Omron CX-Programmer project NuevoProyecto (CX-Programmer 9.50)

# PLC NewPLC1: CP1L-E EM

## Program P1_Apendice (cyclic task 0)
Local symbols
Etapa_0 10.00 BOOL
Etapa_1 10.01 BOOL
Etapa_2 10.02 BOOL
Etapa_3 10.03 BOOL
Etapa_4 10.04 BOOL
F1 0.01 BOOL
F2 0.02 BOOL
Rd 100.00 BOOL
Ri 100.01 BOOL
m 0.00 BOOL

### Section Sección1_Programa_principal
; Programa principal (Etapas 0 ... 4)

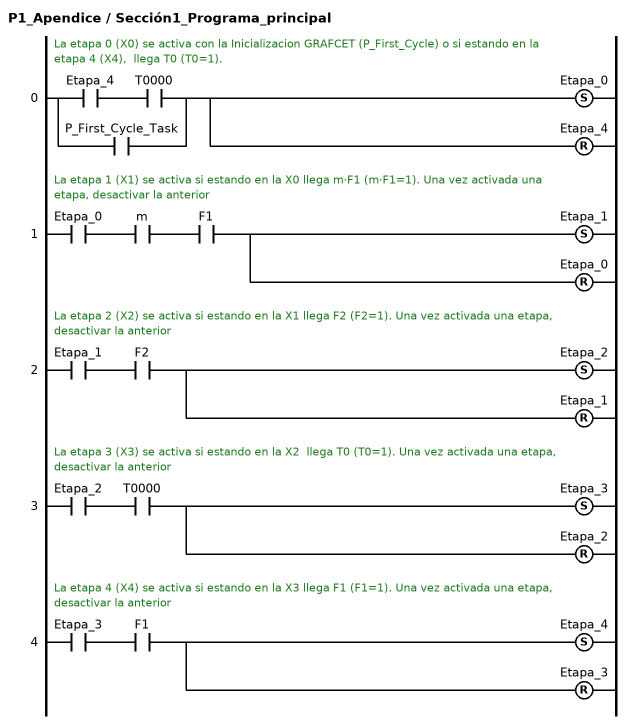
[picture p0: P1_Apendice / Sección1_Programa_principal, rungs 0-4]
; rung 0: La etapa 0 (X0) se activa con la Inicializacion GRAFCET (P_First_Cycle) o si estando en la etapa 4 (X4),  llega T0 (T0=1).
LD Etapa_4
AND T0000
OR P_First_Cycle_Task
SET Etapa_0
RSET Etapa_4  // Una vez activada una etapa, desactivar la anterior
; rung 1: La etapa 1 (X1) se activa si estando en la X0 llega m·F1 (m·F1=1). Una vez activada una etapa, desactivar la anterior
LD Etapa_0
AND m
AND F1
SET Etapa_1
RSET Etapa_0
; rung 2: La etapa 2 (X2) se activa si estando en la X1 llega F2 (F2=1). Una vez activada una etapa, desactivar la anterior
LD Etapa_1
AND F2
SET Etapa_2
RSET Etapa_1
; rung 3: La etapa 3 (X3) se activa si estando en la X2  llega T0 (T0=1). Una vez activada una etapa, desactivar la anterior
LD Etapa_2
AND T0000
SET Etapa_3
RSET Etapa_2
; rung 4: La etapa 4 (X4) se activa si estando en la X3 llega F1 (F1=1). Una vez activada una etapa, desactivar la anterior
LD Etapa_3
AND F1
SET Etapa_4
RSET Etapa_3

### Section Sección2_Temporizador

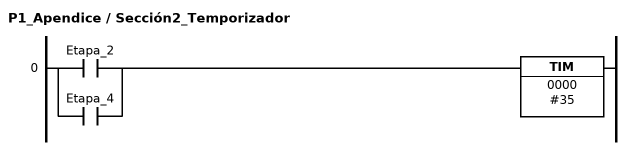
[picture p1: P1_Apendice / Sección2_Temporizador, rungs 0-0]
; rung 0
LD Etapa_2
OR Etapa_4
TIM 0000 #35

### Section Sección3_Salidas

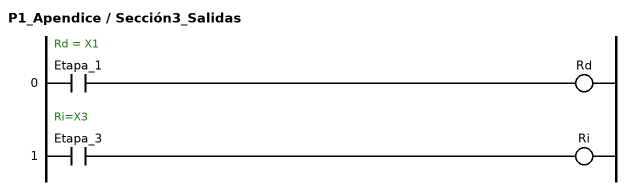
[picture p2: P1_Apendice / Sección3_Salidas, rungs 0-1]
; rung 0: Rd = X1
LD Etapa_1
OUT Rd
; rung 1: Ri=X3
LD Etapa_3
OUT Ri

### Section Sección4_END
; rung 0: Fin de programa
END(001)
